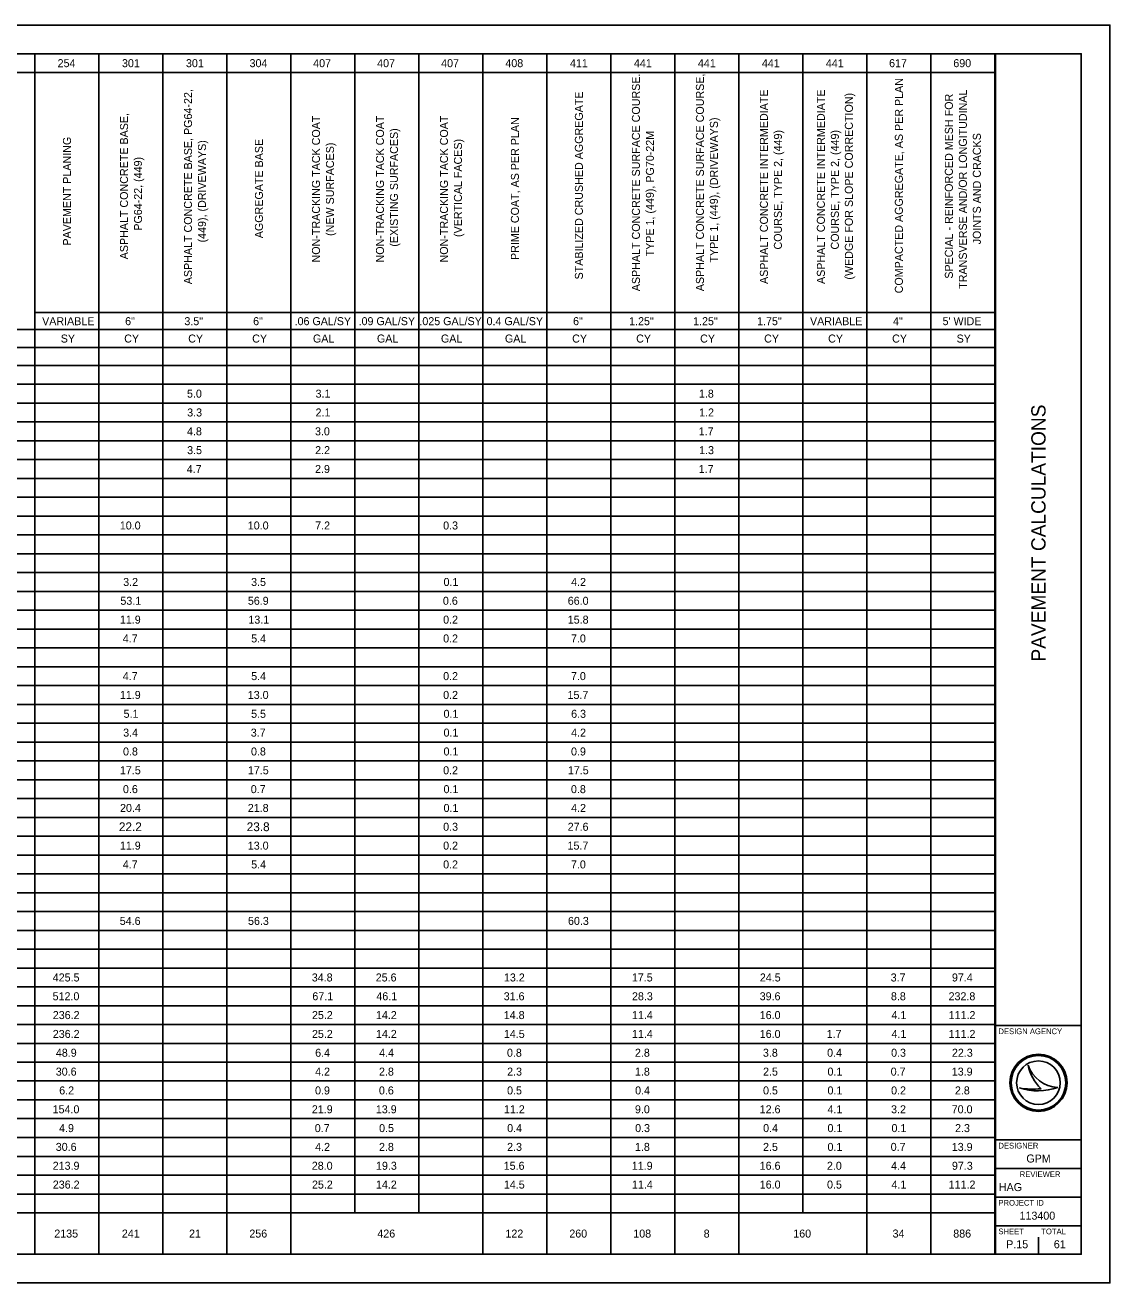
# Model space of a CAD drawing. Extents: x 0 to 34, y 0 to 22.
# Drawn here: x 15.01 to 34, y 0 to 22 of the extents above; entities that cross this region are included whole.
import ezdxf

# ---------------------------------------------------------------- set-up
doc = ezdxf.new("R2010")
doc.units = 0
for name, color, linetype in [('SH_Border', 7, 'Continuous'), ('SH_Cut_Line', 7, 'Continuous'), ('SH_Data', 7, 'Continuous'), ('SH_Text', 7, 'Continuous')]:
    doc.layers.add(name, color=color, linetype=linetype)

msp = doc.modelspace()

# ---------------------------------------------------------------- linework, layer by layer
at = {"layer": 'SH_Border'}
for p, q in [((32, 0.5), (32, 21.5)), ((32, 4.5), (33.5, 4.5)), ((32, 2.5), (33.5, 2.5)), ((32, 2), (33.5, 2)), ((32, 1.5), (33.5, 1.5)), ((32, 1), (33.5, 1))]:
    msp.add_line(p, q, dxfattribs=at)
msp.add_lwpolyline([(1.5, 21.5), (33.5, 21.5), (33.5, 0.5), (1.5, 0.5)], close=True, dxfattribs=at)
at = {"layer": 'SH_Cut_Line'}
msp.add_lwpolyline([(0, 0), (34, 0), (34, 22), (0, 22)], close=True, dxfattribs=at)
at = {"layer": 'SH_Data'}
for p, q in [((32.567, 3.81), (32.567, 3.81)), ((32.417, 3.41), (32.417, 3.41)), ((32.75, 3.5), (32.75, 3.5)), ((33.087, 3.419), (33.087, 3.419)), ((32.375, 0.675), (32.375, 0.675)), ((32.75, 0.5), (32.75, 0.8))]:
    msp.add_line(p, q, dxfattribs=at)
for radius in [0.5, 0.477, 0.477, 0.382]:
    msp.add_circle((32.75, 3.5), radius, dxfattribs=at)
for centre, radius, start, end in [((33.116, 3.998), 0.58, 198.9257, 198.9319), ((33.347, 3.97), 0.796, 191.6379, 191.6421), ((33.116, 3.998), 0.58, 198.9319, 267.1657), ((33.347, 3.97), 0.796, 191.6421, 226.0947), ((32.739, 4.37), 1.013, 251.4576, 290.0832), ((32.648, 4.654), 1.266, 259.4964, 259.4995), ((32.739, 4.37), 1.013, 251.4527, 251.4576), ((32.648, 4.654), 1.266, 259.4995, 276.6672)]:
    msp.add_arc(centre, radius, start, end, dxfattribs=at)
at = {"layer": 'SH_Text'}
for p, q in [((1.5, 21.5), (31.987, 21.5)), ((15.187, 21.5), (15.187, 0.5)), ((16.307, 21.5), (16.307, 0.5)), ((17.427, 21.5), (17.427, 0.5)), ((18.547, 21.5), (18.547, 0.5)), ((19.667, 21.5), (19.667, 0.5)), ((20.787, 21.5), (20.787, 1.225)), ((21.907, 21.5), (21.907, 1.225)), ((23.027, 21.5), (23.027, 0.5)), ((24.147, 21.5), (24.147, 0.5)), ((25.267, 21.5), (25.267, 0.5)), ((26.387, 21.5), (26.387, 0.5)), ((27.507, 21.5), (27.507, 0.5)), ((28.627, 21.5), (28.627, 1.225)), ((29.747, 21.5), (29.747, 0.5)), ((30.867, 21.5), (30.867, 0.5)), ((31.987, 21.5), (31.987, 0.5)), ((10.707, 21.171), (31.987, 21.171)), ((15.187, 16.971), (31.987, 16.971)), ((7.693, 16.674), (31.987, 16.674)), ((1.5, 16.361), (31.987, 16.361)), ((1.5, 16.048), (31.987, 16.048)), ((1.5, 15.719), (31.987, 15.719)), ((1.5, 15.389), (31.987, 15.389)), ((1.5, 15.06), (31.987, 15.06)), ((1.5, 14.731), (31.987, 14.731)), ((1.5, 14.401), (31.987, 14.401)), ((1.5, 14.072), (31.987, 14.072)), ((1.5, 13.742), (31.987, 13.742)), ((1.5, 13.413), (31.987, 13.413)), ((1.5, 13.084), (31.987, 13.084)), ((1.5, 12.754), (31.987, 12.754)), ((1.5, 12.425), (31.987, 12.425)), ((1.5, 12.095), (31.987, 12.095)), ((1.5, 11.766), (31.987, 11.766)), ((1.5, 11.436), (31.987, 11.436)), ((1.5, 11.107), (31.987, 11.107)), ((1.5, 10.778), (31.987, 10.778)), ((1.5, 10.448), (31.987, 10.448)), ((1.5, 10.119), (31.987, 10.119)), ((1.5, 9.789), (31.987, 9.789)), ((1.5, 9.46), (31.987, 9.46)), ((1.5, 9.131), (31.987, 9.131)), ((1.5, 8.801), (31.987, 8.801)), ((1.5, 8.472), (31.987, 8.472)), ((1.5, 8.142), (31.987, 8.142)), ((1.5, 7.813), (31.987, 7.813)), ((1.5, 7.484), (31.987, 7.484)), ((1.5, 7.154), (31.987, 7.154)), ((1.5, 6.825), (31.987, 6.825)), ((1.5, 6.495), (31.987, 6.495)), ((1.5, 6.166), (31.987, 6.166)), ((1.5, 5.836), (31.987, 5.836)), ((1.5, 5.507), (31.987, 5.507)), ((1.5, 5.178), (31.987, 5.178)), ((1.5, 4.848), (31.987, 4.848)), ((1.5, 4.519), (31.987, 4.519)), ((1.5, 4.189), (31.987, 4.189)), ((1.5, 3.86), (31.987, 3.86)), ((1.5, 3.531), (31.987, 3.531)), ((1.5, 3.201), (31.987, 3.201)), ((1.5, 2.872), (31.987, 2.872)), ((1.5, 2.542), (31.987, 2.542)), ((1.5, 2.213), (31.987, 2.213)), ((1.5, 1.884), (31.987, 1.884)), ((1.5, 1.554), (31.987, 1.554)), ((1.5, 1.225), (31.987, 1.225)), ((1.5, 0.5), (31.987, 0.5))]:
    msp.add_line(p, q, dxfattribs=at)

# ---------------------------------------------------------------- texts
at = {"layer": 'SH_Data'}
msp.add_text('PAVEMENT CALCULATIONS', height=0.25, rotation=90, dxfattribs=at).set_placement((32.875, 10.868))
for s, height, p in [('DESIGN AGENCY', 0.1, (32.05, 4.35)), ('DESIGNER', 0.1, (32.05, 2.35)), ('GPM', 0.14, (32.538, 2.105)), ('REVIEWER', 0.1, (32.422, 1.85)), ('HAG', 0.14, (32.057, 1.605)), ('PROJECT ID', 0.1, (32.05, 1.35)), ('113400', 0.14, (32.419, 1.105)), ('SHEET', 0.1, (32.05, 0.85)), ('TOTAL', 0.1, (32.8, 0.85)), ('P.15', 0.14, (32.185, 0.605)), ('61', 0.14, (33.019, 0.605))]:
    msp.add_text(s, height=height, dxfattribs=at).set_placement(p)
at = {"layer": 'SH_Text'}
for s, height, p in [('254', 0.14, (15.583, 21.265)), ('301', 0.14, (16.71, 21.265)), ('301', 0.14, (17.83, 21.265)), ('304', 0.14, (18.943, 21.265)), ('407', 0.14, (20.056, 21.265)), ('407', 0.14, (21.176, 21.265)), ('407', 0.14, (22.296, 21.265)), ('408', 0.14, (23.42, 21.265)), ('411', 0.14, (24.55, 21.265)), ('441', 0.14, (25.67, 21.265)), ('441', 0.14, (26.79, 21.265)), ('441', 0.14, (27.91, 21.265)), ('441', 0.14, (29.03, 21.265)), ('617', 0.14, (30.136, 21.265)), ('690', 0.14, (31.26, 21.265)), ('VARIABLE', 0.14, (15.312, 16.752)), ('6"', 0.14, (16.765, 16.752)), ('3.5"', 0.14, (17.802, 16.752)), ('6"', 0.14, (19.005, 16.752)), ('.06 GAL/SY', 0.14, (19.731, 16.752)), ('.09 GAL/SY', 0.14, (20.851, 16.752)), ('.025 GAL/SY', 0.14, (21.915, 16.752)), ('0.4 GAL/SY', 0.14, (23.091, 16.752)), ('6"', 0.14, (24.605, 16.752)), ('1.25"', 0.14, (25.586, 16.752)), ('1.25"', 0.14, (26.706, 16.752)), ('1.75"', 0.14, (27.826, 16.752)), ('VARIABLE', 0.14, (28.752, 16.752)), ('4"', 0.14, (30.205, 16.752)), ("5' WIDE", 0.14, (31.072, 16.752)), ('SY', 0.14, (15.638, 16.448)), ('CY', 0.14, (16.749, 16.448)), ('CY', 0.14, (17.869, 16.448)), ('CY', 0.14, (18.989, 16.448)), ('GAL', 0.14, (20.052, 16.448)), ('GAL', 0.14, (21.172, 16.448)), ('GAL', 0.14, (22.292, 16.448)), ('GAL', 0.14, (23.412, 16.448)), ('CY', 0.14, (24.589, 16.448)), ('CY', 0.14, (25.709, 16.448)), ('CY', 0.14, (26.829, 16.448)), ('CY', 0.14, (27.949, 16.448)), ('CY', 0.14, (29.069, 16.448)), ('CY', 0.14, (30.189, 16.448)), ('SY', 0.14, (31.318, 16.448)), ('5.0', 0.14, (17.848, 15.484)), ('3.1', 0.14, (20.098, 15.484)), ('1.8', 0.14, (26.808, 15.484)), ('3.3', 0.14, (17.851, 15.155)), ('2.1', 0.14, (20.098, 15.155)), ('1.2', 0.14, (26.811, 15.155)), ('4.8', 0.14, (17.848, 14.825)), ('3.0', 0.14, (20.088, 14.825)), ('1.7', 0.14, (26.804, 14.825)), ('3.5', 0.14, (17.85, 14.496)), ('2.2', 0.14, (20.091, 14.496)), ('1.3', 0.14, (26.811, 14.496)), ('4.7', 0.14, (17.844, 14.166)), ('2.9', 0.14, (20.089, 14.166)), ('1.7', 0.14, (26.804, 14.166)), ('10.0', 0.14, (16.672, 13.178)), ('10.0', 0.14, (18.912, 13.178)), ('7.2', 0.14, (20.091, 13.178)), ('0.3', 0.14, (22.331, 13.178)), ('3.2', 0.14, (16.731, 12.19)), ('3.5', 0.14, (18.97, 12.19)), ('0.1', 0.14, (22.338, 12.19)), ('4.2', 0.14, (24.571, 12.19)), ('53.1', 0.14, (16.682, 11.861)), ('56.9', 0.14, (18.913, 11.861)), ('0.6', 0.14, (22.327, 11.861)), ('66.0', 0.14, (24.512, 11.861)), ('11.9', 0.14, (16.673, 11.531)), ('13.1', 0.14, (18.922, 11.531)), ('0.2', 0.14, (22.331, 11.531)), ('15.8', 0.14, (24.512, 11.531)), ('4.7', 0.14, (16.724, 11.202)), ('5.4', 0.14, (18.971, 11.202)), ('0.2', 0.14, (22.331, 11.202)), ('7.0', 0.14, (24.568, 11.202)), ('4.7', 0.14, (16.724, 10.543)), ('5.4', 0.14, (18.971, 10.543)), ('0.2', 0.14, (22.331, 10.543)), ('7.0', 0.14, (24.568, 10.543)), ('11.9', 0.14, (16.673, 10.214)), ('13.0', 0.14, (18.912, 10.214)), ('0.2', 0.14, (22.331, 10.214)), ('15.7', 0.14, (24.508, 10.214)), ('5.1', 0.14, (16.738, 9.884)), ('5.5', 0.14, (18.97, 9.884)), ('0.1', 0.14, (22.338, 9.884)), ('6.3', 0.14, (24.571, 9.884)), ('3.4', 0.14, (16.731, 9.555)), ('3.7', 0.14, (18.964, 9.555)), ('0.1', 0.14, (22.338, 9.555)), ('4.2', 0.14, (24.571, 9.555)), ('0.8', 0.14, (16.728, 9.225)), ('0.8', 0.14, (18.968, 9.225)), ('0.1', 0.14, (22.338, 9.225)), ('0.9', 0.14, (24.569, 9.225)), ('17.5', 0.14, (16.674, 8.896)), ('17.5', 0.14, (18.914, 8.896)), ('0.2', 0.14, (22.331, 8.896)), ('17.5', 0.14, (24.514, 8.896)), ('0.6', 0.14, (16.727, 8.566)), ('0.7', 0.14, (18.964, 8.566)), ('0.1', 0.14, (22.338, 8.566)), ('0.8', 0.14, (24.568, 8.566)), ('20.4', 0.14, (16.676, 8.237)), ('21.8', 0.14, (18.912, 8.237)), ('0.1', 0.14, (22.338, 8.237)), ('4.2', 0.14, (24.571, 8.237)), ('22.2', 0.154, (16.656, 7.901)), ('23.8', 0.154, (18.893, 7.901)), ('0.3', 0.14, (22.331, 7.908)), ('27.6', 0.14, (24.511, 7.908)), ('11.9', 0.14, (16.673, 7.578)), ('13.0', 0.14, (18.912, 7.578)), ('0.2', 0.14, (22.331, 7.578)), ('15.7', 0.14, (24.508, 7.578)), ('4.7', 0.14, (16.724, 7.249)), ('5.4', 0.14, (18.971, 7.249)), ('0.2', 0.14, (22.331, 7.249)), ('7.0', 0.14, (24.568, 7.249)), ('54.6', 0.14, (16.671, 6.261)), ('56.3', 0.14, (18.916, 6.261)), ('60.3', 0.14, (24.516, 6.261)), ('425.5', 0.14, (15.498, 5.272)), ('34.8', 0.14, (20.032, 5.272)), ('25.6', 0.14, (21.151, 5.272)), ('13.2', 0.14, (23.395, 5.272)), ('17.5', 0.14, (25.634, 5.272)), ('24.5', 0.14, (27.874, 5.272)), ('3.7', 0.14, (30.164, 5.272)), ('97.4', 0.14, (31.236, 5.272)), ('512.0', 0.14, (15.496, 4.943)), ('67.1', 0.14, (20.042, 4.943)), ('46.1', 0.14, (21.162, 4.943)), ('31.6', 0.14, (23.391, 4.943)), ('28.3', 0.14, (25.636, 4.943)), ('39.6', 0.14, (27.871, 4.943)), ('8.8', 0.14, (30.168, 4.943)), ('232.8', 0.14, (31.177, 4.943)), ('236.2', 0.14, (15.499, 4.614)), ('25.2', 0.14, (20.035, 4.614)), ('14.2', 0.14, (21.155, 4.614)), ('14.8', 0.14, (23.392, 4.614)), ('11.4', 0.14, (25.636, 4.614)), ('16.0', 0.14, (27.872, 4.614)), ('4.1', 0.14, (30.178, 4.614)), ('111.2', 0.14, (31.179, 4.614)), ('236.2', 0.14, (15.499, 4.284)), ('25.2', 0.14, (20.035, 4.284)), ('14.2', 0.14, (21.155, 4.284)), ('14.5', 0.14, (23.394, 4.284)), ('11.4', 0.14, (25.636, 4.284)), ('16.0', 0.14, (27.872, 4.284)), ('1.7', 0.14, (29.044, 4.284)), ('4.1', 0.14, (30.178, 4.284)), ('111.2', 0.14, (31.179, 4.284)), ('48.9', 0.14, (15.553, 3.955)), ('6.4', 0.14, (20.091, 3.955)), ('4.4', 0.14, (21.211, 3.955)), ('0.8', 0.14, (23.448, 3.955)), ('2.8', 0.14, (25.688, 3.955)), ('3.8', 0.14, (27.928, 3.955)), ('0.4', 0.14, (29.051, 3.955)), ('0.3', 0.14, (30.171, 3.955)), ('22.3', 0.14, (31.236, 3.955)), ('30.6', 0.14, (15.551, 3.625)), ('4.2', 0.14, (20.091, 3.625)), ('2.8', 0.14, (21.208, 3.625)), ('2.3', 0.14, (23.451, 3.625)), ('1.8', 0.14, (25.688, 3.625)), ('2.5', 0.14, (27.93, 3.625)), ('0.1', 0.14, (29.058, 3.625)), ('0.7', 0.14, (30.164, 3.625)), ('13.9', 0.14, (31.233, 3.625)), ('6.2', 0.14, (15.611, 3.296)), ('0.9', 0.14, (20.089, 3.296)), ('0.6', 0.14, (21.207, 3.296)), ('0.5', 0.14, (23.45, 3.296)), ('0.4', 0.14, (25.691, 3.296)), ('0.5', 0.14, (27.93, 3.296)), ('0.1', 0.14, (29.058, 3.296)), ('0.2', 0.14, (30.171, 3.296)), ('2.8', 0.14, (31.288, 3.296)), ('154.0', 0.14, (15.496, 2.966)), ('21.9', 0.14, (20.033, 2.966)), ('13.9', 0.14, (21.153, 2.966)), ('11.2', 0.14, (23.395, 2.966)), ('9.0', 0.14, (25.688, 2.966)), ('12.6', 0.14, (27.871, 2.966)), ('4.1', 0.14, (29.058, 2.966)), ('3.2', 0.14, (30.171, 2.966)), ('70.0', 0.14, (31.232, 2.966)), ('4.9', 0.14, (15.609, 2.637)), ('0.7', 0.14, (20.084, 2.637)), ('0.5', 0.14, (21.21, 2.637)), ('0.4', 0.14, (23.451, 2.637)), ('0.3', 0.14, (25.691, 2.637)), ('0.4', 0.14, (27.931, 2.637)), ('0.1', 0.14, (29.058, 2.637)), ('0.1', 0.14, (30.178, 2.637)), ('2.3', 0.14, (31.291, 2.637)), ('30.6', 0.14, (15.551, 2.308)), ('4.2', 0.14, (20.091, 2.308)), ('2.8', 0.14, (21.208, 2.308)), ('2.3', 0.14, (23.451, 2.308)), ('1.8', 0.14, (25.688, 2.308)), ('2.5', 0.14, (27.93, 2.308)), ('0.1', 0.14, (29.058, 2.308)), ('0.7', 0.14, (30.164, 2.308)), ('13.9', 0.14, (31.233, 2.308)), ('213.9', 0.14, (15.497, 1.978)), ('28.0', 0.14, (20.032, 1.978)), ('19.3', 0.14, (21.156, 1.978)), ('15.6', 0.14, (23.391, 1.978)), ('11.9', 0.14, (25.633, 1.978)), ('16.6', 0.14, (27.871, 1.978)), ('2.0', 0.14, (29.048, 1.978)), ('4.4', 0.14, (30.171, 1.978)), ('97.3', 0.14, (31.236, 1.978)), ('236.2', 0.14, (15.499, 1.649)), ('25.2', 0.14, (20.035, 1.649)), ('14.2', 0.14, (21.155, 1.649)), ('14.5', 0.14, (23.394, 1.649)), ('11.4', 0.14, (25.636, 1.649)), ('16.0', 0.14, (27.872, 1.649)), ('0.5', 0.14, (29.05, 1.649)), ('4.1', 0.14, (30.178, 1.649)), ('111.2', 0.14, (31.179, 1.649)), ('2135', 0.14, (15.525, 0.792)), ('241', 0.14, (16.708, 0.792)), ('21', 0.14, (17.884, 0.792)), ('256', 0.14, (18.939, 0.792)), ('426', 0.14, (21.179, 0.792)), ('122', 0.14, (23.421, 0.792)), ('260', 0.14, (24.539, 0.792)), ('108', 0.14, (25.659, 0.792)), ('8', 0.14, (26.891, 0.792)), ('160', 0.14, (28.459, 0.792)), ('34', 0.14, (30.197, 0.792)), ('886', 0.14, (31.259, 0.792))]:
    msp.add_text(s, height=height, dxfattribs=at).set_placement(p)
for s, p in [('ASPHALT CONCRETE SURFACE COURSE.', (25.775, 17.346)), ('ASPHALT CONCRETE SURFACE COURSE,', (26.895, 17.346)), ('COMPACTED AGGREGATE, AS PER PLAN', (30.377, 17.309)), ('ASPHALT CONCRETE BASE, PG64-22,', (17.935, 17.468)), ('STABILIZED CRUSHED AGGREGATE', (24.777, 17.552)), ('ASPHALT CONCRETE INTERMEDIATE', (28.015, 17.473)), ('ASPHALT CONCRETE INTERMEDIATE', (29.012, 17.473)), ('(WEDGE FOR SLOPE CORRECTION)', (29.502, 17.549)), ('SPECIAL - REINFORCED MESH FOR', (31.252, 17.565)), ('TRANSVERSE AND/OR LONGITUDINAL', (31.497, 17.388)), ('ASPHALT CONCRETE BASE,', (16.815, 17.904)), ('NON-TRACKING TACK COAT', (20.175, 17.849)), ('NON-TRACKING TACK COAT', (21.295, 17.849)), ('NON-TRACKING TACK COAT', (22.415, 17.849)), ('PRIME COAT, AS PER PLAN', (23.657, 17.892)), ('TYPE 1, (449), (DRIVEWAYS)', (27.14, 17.847)), ('PAVEMENT PLANING', (15.817, 18.144)), ('(EXISTING SURFACES)', (21.54, 18.126)), ('TYPE 1, (449), PG70-22M', (26.02, 17.955)), ('COURSE, TYPE 2, (449)', (28.26, 18.075)), ('COURSE, TYPE 2, (449)', (29.257, 18.075)), ('JOINTS AND CRACKS', (31.742, 18.166)), ('(449), (DRIVEWAYS)', (18.18, 18.199)), ('AGGREGATE BASE', (19.177, 18.273)), ('(NEW SURFACES)', (20.42, 18.313)), ('(VERTICAL FACES)', (22.66, 18.294)), ('PG64-22, (449)', (17.06, 18.405))]:
    msp.add_text(s, height=0.14, rotation=90, dxfattribs=at).set_placement(p)

doc.saveas('drawing.dxf')
